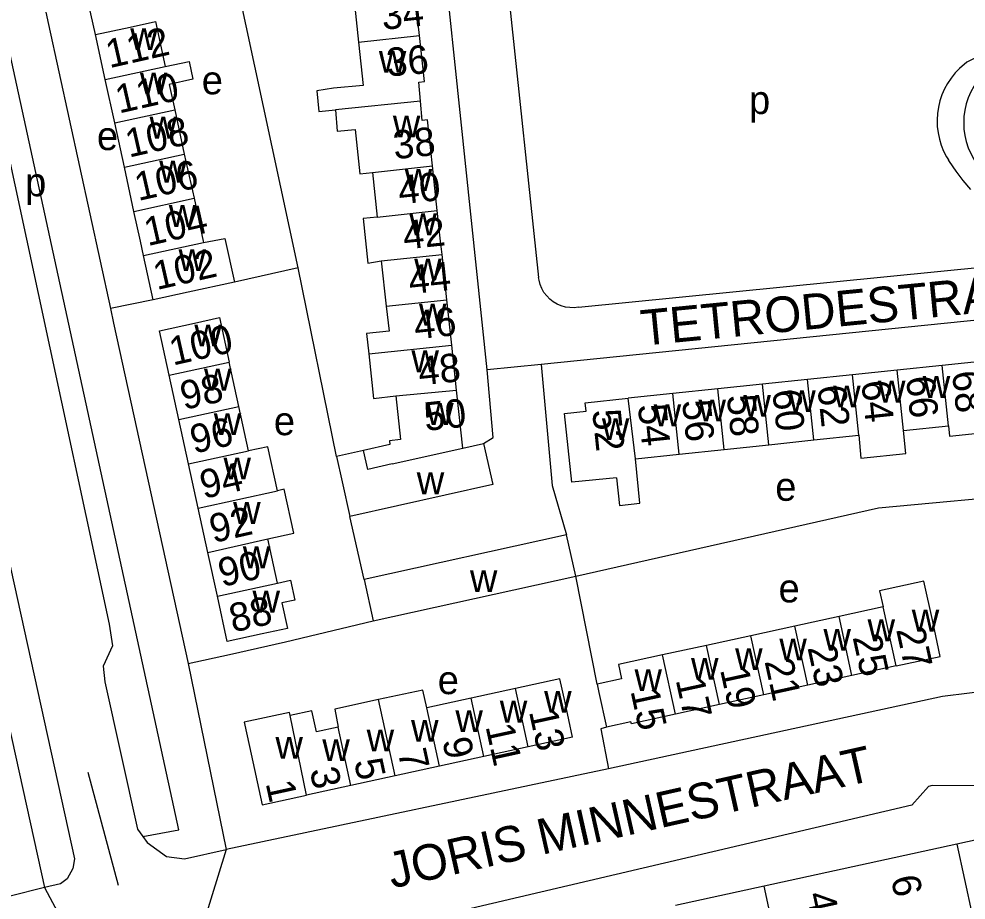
# Model space of a CAD drawing. Extents: x 159294 to 161936, y 384538 to 386517.
# Drawn here: x 160707.3 to 160840.4, y 385907.4 to 386031.2 of the extents above; entities that cross this region are included whole.
import ezdxf

# ---------------------------------------------------------------- set-up
doc = ezdxf.new("R2010")
doc.units = 0
for name, color, linetype in [('BLT_Basislijn', 7, 'Continuous'), ('BLT_Bebouwing', 7, 'Continuous'), ('BLT_Centroide', 7, 'Continuous'), ('BLT_Huisnummer', 7, 'Continuous'), ('BLT_Huisnummer_ tussenligend', 7, 'Continuous'), ('BLT_Huisnummer_reeks', 7, 'Continuous'), ('BLT_Onderverdeling_panden', 7, 'Continuous'), ('BLT_Straatnaam', 7, 'Continuous'), ('BLT_Vlakafsluiter', 7, 'Continuous')]:
    doc.layers.add(name, color=color, linetype=linetype)

msp = doc.modelspace()

# ---------------------------------------------------------------- linework, layer by layer
at = {"layer": 'BLT_Basislijn'}
for p, q in [((160775.29, 386042.75), (160780.36, 385994.88)), ((160718.09, 386029.02), (160717.12, 386033.4)), ((160746.59, 385996.22), (160737.63, 385994.24)), ((160751.96, 385969.73), (160746.59, 385996.22)), ((160785.98, 385990.69), (160850.47, 385997.12)), ((160726.21, 385991.76), (160720.2, 385990.52)), ((160780.73, 385982.66), (160773.13, 385981.91)), ((160755.85, 385952.43), (160753.85, 385961.28)), ((160700, 385958.71), (160710.91, 385909.14)), ((160788.57, 385937.7), (160785.58, 385952.89)), ((160731.13, 385940.64), (160736.48, 385914.45)), ((160789.89, 385931.66), (160789.11, 385931.43)), ((160789.11, 385931.43), (160790.19, 385925.81)), ((160790.19, 385925.81), (160736.48, 385914.45)), ((160717.03, 385925.33), (160721.29, 385909.44)), ((160710.91, 385909.14), (160706.13, 385907.93))]:
    msp.add_line(p, q, dxfattribs=at)
for points in [[(160773.13, 385981.91), (160763.33, 386075.31), (160762.11, 386075.61)], [(160724.75, 385916.3), (160729.82, 385917.26), (160700, 386054.05)], [(160700, 386039.15), (160720.02, 385946.17), (160720.5, 385943.08), (160719.17, 385940.25), (160719.41, 385938.04), (160724, 385917.35), (160724.75, 385916.3)], [(160746.59, 385996.22), (160738.06, 386035.99), (160737.84, 386037.75)], [(160711.11, 386032.17), (160711.48, 386030.46), (160720.2, 385990.52)], [(160851.41, 386028.7), (160847.92, 386027.88), (160845.04, 386025.75), (160842.92, 386026.31), (160840.52, 386025.15), (160839.52, 386024.28)], [(160839.52, 386024.28), (160838.89, 386023.63), (160838.33, 386022.92), (160837.82, 386022.17), (160837.39, 386021.38), (160837.03, 386020.55), (160836.74, 386019.7), (160836.54, 386018.82), (160836.4, 386017.92), (160836.35, 386017.02), (160836.38, 386016.12), (160836.49, 386015.22), (160836.68, 386014.34), (160836.94, 386013.48), (160837.28, 386012.64), (160837.7, 386011.84), (160837.94, 386011.44)], [(160842.01, 386022.49), (160841.52, 386021.74), (160841.09, 386020.96), (160840.74, 386020.14), (160840.46, 386019.29), (160840.26, 386018.41), (160840.14, 386017.53), (160840.1, 386016.64), (160840.14, 386015.74), (160840.26, 386014.86), (160840.45, 386013.98), (160840.73, 386013.13), (160841.08, 386012.31), (160841.5, 386011.52), (160841.99, 386010.77), (160842.54, 386010.07), (160843.15, 386009.42), (160843.83, 386008.83), (160844.55, 386008.3), (160845.31, 386007.84), (160846.12, 386007.45), (160846.6, 386007.26)], [(160841.11, 386007.25), (160840.04, 386008.51), (160839.04, 386009.83), (160838.1, 386011.19), (160837.94, 386011.44)], [(160785.98, 385990.69), (160785.36, 385990.62), (160784.74, 385990.64), (160784.12, 385990.73), (160783.52, 385990.9), (160782.96, 385991.15), (160782.42, 385991.47), (160781.93, 385991.85), (160781.5, 385992.3), (160781.12, 385992.79), (160780.81, 385993.33), (160780.58, 385993.91), (160780.42, 385994.51), (160780.36, 385994.88)], [(160720.2, 385990.52), (160720.65, 385988.45), (160731.13, 385940.64)], [(160859.23, 385988.45), (160858.82, 385990.52), (160856.7, 385990.38), (160780.73, 385982.66)], [(160700, 385981.81), (160715.13, 385913.15), (160714.89, 385911.82), (160714.13, 385910.35), (160713.17, 385909.64), (160710.91, 385909.14)], [(160772.63, 385971.54), (160773.97, 385972.4), (160773.13, 385981.91)], [(160780.73, 385982.66), (160782.28, 385965.66), (160784.3, 385958.7)], [(160785.58, 385952.89), (160828.14, 385962.5), (160850.38, 385964.54), (160853.69, 385964.6), (160860.01, 385962.42)], [(160731.13, 385940.64), (160736.91, 385941.89), (160744.81, 385943.68), (160757.12, 385946.62)], [(160887.99, 385925.36), (160883.44, 385926.7), (160883.29, 385928.09), (160883.51, 385928.54), (160861.9, 385934.99), (160852.41, 385936.78), (160844.7, 385936.94), (160837.12, 385935.98), (160790.19, 385925.81)], [(160878.09, 385873.27), (160882.75, 385872.03), (160884.03, 385872.93), (160885.3, 385874.52), (160884.95, 385877.35), (160895.88, 385895.1), (160896.53, 385895.86), (160901.29, 385903.4), (160899.44, 385905.93), (160897.31, 385907.67), (160894.48, 385908.01), (160892.15, 385906.21), (160890.48, 385906.26), (160855.53, 385917.61), (160853.29, 385921.28), (160852.6, 385921.78), (160843.49, 385923.4), (160835.67, 385923.48), (160835.16, 385923.35), (160832.82, 385920.7), (160749.73, 385901.19), (160744.7, 385901.94), (160733.87, 385898.4), (160732.63, 385897.5)], [(160724.75, 385916.3), (160725.35, 385915.47), (160728.08, 385913.47), (160730.62, 385913.14), (160736.48, 385914.45)]]:
    msp.add_lwpolyline(points, dxfattribs=at)
at = {"layer": 'BLT_Bebouwing'}
for p, q in [((160763.61, 386028.9), (160762.92, 386035.21)), ((160754.38, 386034.29), (160755.06, 386027.98)), ((160719.46, 386022.7), (160718.09, 386029.02)), ((160720.8, 386016.6), (160719.46, 386022.7)), ((160763.99, 386016.94), (160763.76, 386019.65)), ((160729.23, 386018.44), (160730.58, 386012.23)), ((160722.15, 386010.39), (160720.8, 386016.6)), ((160730.58, 386012.23), (160731.94, 386006.02)), ((160723.5, 386004.18), (160722.15, 386010.39)), ((160757.01, 386009.66), (160757.67, 386003.37)), ((160766.13, 386004.28), (160765.46, 386010.57)), ((160726.21, 385991.76), (160724.86, 385997.97)), ((160767.48, 385991.74), (160766.8, 385998.1)), ((160758.26, 385997.2), (160758.94, 385990.84)), ((160768.16, 385985.38), (160767.48, 385991.74)), ((160728.46, 385981.16), (160727.1, 385987.4)), ((160768.84, 385979.03), (160768.16, 385985.38)), ((160738.25, 385976.76), (160736.89, 385983)), ((160843.36, 385983.18), (160837.06, 385982.52)), ((160830.75, 385981.86), (160824.45, 385981.2)), ((160837.06, 385982.52), (160830.75, 385981.86)), ((160729.82, 385974.93), (160728.46, 385981.16)), ((160818.15, 385980.55), (160811.84, 385979.89)), ((160824.45, 385981.2), (160818.15, 385980.55)), ((160769.72, 385970.89), (160768.84, 385979.03)), ((160805.54, 385979.23), (160799.23, 385978.57)), ((160811.84, 385979.89), (160805.54, 385979.23)), ((160786.9, 385977.28), (160792.93, 385977.91)), ((160799.23, 385978.57), (160792.93, 385977.91)), ((160739.61, 385970.53), (160738.25, 385976.76)), ((160731.18, 385968.69), (160729.82, 385974.93)), ((160831.64, 385973.36), (160837.95, 385974.02)), ((160819.04, 385972.04), (160825.34, 385972.7)), ((160769.72, 385970.89), (160772.63, 385971.54)), ((160806.43, 385970.72), (160812.73, 385971.38)), ((160812.73, 385971.38), (160819.04, 385972.04)), ((160793.96, 385969.41), (160800.12, 385970.06)), ((160800.12, 385970.06), (160806.43, 385970.72)), ((160732.54, 385962.45), (160731.18, 385968.69)), ((160791.33, 385966.74), (160785.03, 385966.09)), ((160733.9, 385956.21), (160732.54, 385962.45)), ((160743.67, 385951.93), (160742.32, 385958.12)), ((160784.3, 385958.7), (160755.85, 385952.43)), ((160785.58, 385952.89), (160784.3, 385958.7)), ((160735.24, 385950.09), (160733.9, 385956.21)), ((160755.85, 385952.43), (160757.12, 385946.62)), ((160757.12, 385946.62), (160785.58, 385952.89)), ((160828.78, 385948.6), (160822.58, 385947.24)), ((160822.58, 385947.24), (160816.38, 385945.89)), ((160816.38, 385945.89), (160810.18, 385944.53)), ((160810.18, 385944.53), (160803.98, 385943.17)), ((160803.98, 385943.17), (160797.77, 385941.82)), ((160830.61, 385940.27), (160824.4, 385938.91)), ((160824.4, 385938.91), (160818.2, 385937.55)), ((160818.2, 385937.55), (160812, 385936.2)), ((160777.12, 385937.11), (160770.89, 385935.76)), ((160812, 385936.2), (160805.8, 385934.84)), ((160770.89, 385935.76), (160764.66, 385934.4)), ((160805.8, 385934.84), (160799.6, 385933.48)), ((160785.14, 385930.25), (160778.92, 385928.89)), ((160778.92, 385928.89), (160772.69, 385927.53)), ((160772.69, 385927.53), (160766.45, 385926.17)), ((160766.45, 385926.17), (160760.22, 385924.81)), ((160760.22, 385924.81), (160753.99, 385923.46)), ((160753.99, 385923.46), (160747.76, 385922.1)), ((160839.15, 385915.21), (160812.05, 385909.31)), ((160812.05, 385909.31), (160799.6, 385906.6))]:
    msp.add_line(p, q, dxfattribs=at)
for points in [[(160718.09, 386029.02), (160722.97, 386030.09), (160726.52, 386030.86), (160727.9, 386024.54)], [(160763.76, 386019.65), (160763.53, 386022.32), (160764.31, 386022.41), (160763.61, 386028.9)], [(160755.06, 386027.98), (160755.72, 386021.87), (160751.52, 386021.48), (160749.21, 386021.12), (160749.5, 386018.21), (160751.8, 386018.44)], [(160727.9, 386024.54), (160731.24, 386025.26), (160731.79, 386022.75), (160728.45, 386022.02), (160729.23, 386018.44)], [(160751.8, 386018.44), (160752.08, 386015.47), (160754.59, 386015.7)], [(160765.46, 386010.57), (160764.77, 386017.02), (160763.99, 386016.94)], [(160754.59, 386015.7), (160755.25, 386009.47), (160757.01, 386009.66)], [(160731.94, 386006.02), (160733.25, 386000), (160733.29, 385999.81)], [(160724.86, 385997.97), (160724.42, 386000), (160723.5, 386004.18)], [(160766.8, 385998.1), (160766.59, 386000), (160766.13, 386004.28)], [(160757.67, 386003.37), (160755.7, 386003.16), (160756.36, 385996.88), (160758.26, 385997.2)], [(160733.29, 385999.81), (160736.29, 386000.37), (160737.63, 385994.24)], [(160737.63, 385994.24), (160731.1, 385992.82), (160726.21, 385991.76)], [(160758.94, 385990.84), (160759.35, 385987.33), (160756.19, 385986.99), (160756.49, 385984.17)], [(160727.1, 385987.4), (160731.99, 385988.47), (160735.53, 385989.24), (160736.89, 385983)], [(160756.49, 385984.17), (160757.16, 385977.89), (160760.31, 385978.23)], [(160760.31, 385978.23), (160760.95, 385972.09), (160759.42, 385971.93), (160759.48, 385971.41), (160755.75, 385970.58)], [(160785.03, 385966.09), (160784.02, 385975.76), (160787.03, 385976.08), (160786.9, 385977.28)], [(160837.95, 385974.02), (160838.1, 385972.56), (160844.4, 385973.22), (160844.25, 385974.68)], [(160825.34, 385972.7), (160825.64, 385969.46), (160831.98, 385970.12), (160831.64, 385973.36)], [(160743.66, 385964.89), (160742.31, 385971.09), (160739.61, 385970.53)], [(160772.63, 385971.54), (160773.92, 385965.76), (160753.85, 385961.28)], [(160755.75, 385970.58), (160751.96, 385969.73)], [(160751.96, 385969.73), (160752.76, 385966.16), (160753.85, 385961.28)], [(160791.33, 385966.74), (160791.74, 385962.84), (160794.61, 385963.14), (160793.96, 385969.41)], [(160742.32, 385958.12), (160745.98, 385958.92), (160744.63, 385965.11), (160743.66, 385964.89)], [(160743.67, 385951.93), (160745.48, 385952.32), (160746.09, 385949.53), (160744.28, 385949.14), (160745.06, 385945.56), (160741.51, 385944.79), (160736.62, 385943.73), (160735.24, 385950.09)], [(160830.61, 385940.27), (160836.81, 385941.62), (160835.74, 385946.51), (160834.49, 385952.21), (160828.28, 385950.85), (160828.78, 385948.6)], [(160797.77, 385941.82), (160791.57, 385940.46), (160792.01, 385938.46), (160788.57, 385937.7)], [(160785.14, 385930.25), (160784.08, 385935.13), (160783.35, 385938.47), (160777.12, 385937.11)], [(160788.57, 385937.7), (160788.82, 385936.55), (160789.89, 385931.66)], [(160764.66, 385934.4), (160764.09, 385936.89), (160757.88, 385935.54)], [(160757.88, 385935.54), (160751.72, 385934.2), (160752.2, 385931.68)], [(160745.44, 385933.31), (160745.34, 385933.75), (160738.99, 385932.38), (160739.73, 385928.96)], [(160752.2, 385931.68), (160749.16, 385931.02), (160748.51, 385933.98), (160745.44, 385933.31)], [(160799.6, 385933.48), (160793.4, 385932.12), (160793.33, 385932.42), (160789.89, 385931.66)], [(160739.73, 385928.96), (160741.52, 385920.74), (160747.76, 385922.1)], [(160854.91, 385912.23), (160843.2, 385916.09), (160839.15, 385915.21)]]:
    msp.add_lwpolyline(points, dxfattribs=at)
at = {"layer": 'BLT_Onderverdeling_panden'}
for p, q in [((160755.06, 386027.98), (160763.61, 386028.9)), ((160719.46, 386022.7), (160727.9, 386024.54)), ((160763.76, 386019.65), (160751.8, 386018.44)), ((160720.8, 386016.6), (160729.23, 386018.44)), ((160722.15, 386010.39), (160730.58, 386012.23)), ((160757.01, 386009.66), (160765.46, 386010.57)), ((160723.5, 386004.18), (160731.94, 386006.02)), ((160757.67, 386003.37), (160766.13, 386004.28)), ((160724.86, 385997.97), (160733.29, 385999.81)), ((160758.26, 385997.2), (160766.8, 385998.1)), ((160758.94, 385990.84), (160767.48, 385991.74)), ((160756.49, 385984.17), (160768.16, 385985.38)), ((160728.46, 385981.16), (160736.89, 385983)), ((160831.64, 385973.36), (160830.75, 385981.86)), ((160837.95, 385974.02), (160837.06, 385982.52)), ((160819.04, 385972.04), (160818.15, 385980.55)), ((160825.34, 385972.7), (160824.45, 385981.2)), ((160760.31, 385978.23), (160768.84, 385979.03)), ((160806.43, 385970.72), (160805.54, 385979.23)), ((160812.73, 385971.38), (160811.84, 385979.89)), ((160793.96, 385969.41), (160792.93, 385977.91)), ((160800.12, 385970.06), (160799.23, 385978.57)), ((160729.82, 385974.93), (160738.25, 385976.76)), ((160759.77, 385968.67), (160769.72, 385970.89)), ((160731.18, 385968.69), (160739.61, 385970.53)), ((160732.54, 385962.45), (160743.66, 385964.89)), ((160733.9, 385956.21), (160742.32, 385958.12)), ((160735.24, 385950.09), (160743.67, 385951.93)), ((160830.61, 385940.27), (160828.78, 385948.6)), ((160824.4, 385938.91), (160822.58, 385947.24)), ((160818.2, 385937.55), (160816.38, 385945.89)), ((160812, 385936.2), (160810.18, 385944.53)), ((160805.8, 385934.84), (160803.98, 385943.17)), ((160799.6, 385933.48), (160797.77, 385941.82)), ((160778.92, 385928.89), (160777.12, 385937.11)), ((160760.22, 385924.81), (160757.88, 385935.54)), ((160772.69, 385927.53), (160770.89, 385935.76)), ((160766.45, 385926.17), (160764.66, 385934.4)), ((160747.76, 385922.1), (160745.44, 385933.31)), ((160753.99, 385923.46), (160752.2, 385931.68)), ((160813.9, 385900.78), (160812.05, 385909.31))]:
    msp.add_line(p, q, dxfattribs=at)
for points in [[(160759.77, 385968.67), (160756.35, 385967.91), (160755.75, 385970.58)], [(160839.15, 385915.21), (160841.29, 385905.3)]]:
    msp.add_lwpolyline(points, dxfattribs=at)
at = {"layer": 'BLT_Vlakafsluiter'}
for p, q in [((160736.48, 385914.45), (160733.17, 385903.85)), ((160710.91, 385909.14), (160715.96, 385899.78))]:
    msp.add_line(p, q, dxfattribs=at)

# ---------------------------------------------------------------- texts
at = {"layer": 'BLT_Centroide'}
for s, p in [('w', (160722.98, 386026.84)), ('w', (160757.91, 386023.67)), ('w', (160724.34, 386020.62)), ('e', (160733.03, 386020.63)), ('p', (160809.93, 386017.86)), ('w', (160725.69, 386014.41)), ('w', (160759.88, 386014.56)), ('e', (160718.3, 386012.79)), ('w', (160727.05, 386008.22)), ('p', (160708.2, 386006.3)), ('w', (160761.55, 386007.06)), ('w', (160728.4, 386002)), ('w', (160762.19, 386000.81)), ('w', (160729.76, 385995.78)), ('w', (160762.88, 385994.47)), ('w', (160763.55, 385988.12)), ('w', (160731.99, 385985.19)), ('w', (160762.49, 385981.56)), ('w', (160733.35, 385978.97)), ('w', (160828.05, 385977.3)), ('w', (160834.34, 385977.95)), ('w', (160815.44, 385975.95)), ('w', (160821.75, 385976.61)), ('w', (160802.83, 385974.64)), ('w', (160809.14, 385975.3)), ('w', (160764.56, 385974.16)), ('w', (160796.53, 385973.98)), ('w', (160734.72, 385972.72)), ('e', (160743.16, 385972.71)), ('w', (160789.25, 385972.03)), ('w', (160736.08, 385966.5)), ('w', (160763.24, 385964.41)), ('e', (160813.62, 385963.49)), ('w', (160737.44, 385960.25)), ('w', (160738.8, 385954)), ('w', (160770.71, 385950.66)), ('e', (160814.08, 385949.21)), ('w', (160740.16, 385947.78)), ('w', (160832.8, 385945.11)), ('w', (160826.59, 385943.75)), ('w', (160820.39, 385942.41)), ('w', (160814.19, 385941.05)), ('w', (160807.98, 385939.69)), ('w', (160801.78, 385938.33)), ('e', (160766.19, 385936.31)), ('w', (160793.84, 385936.75)), ('w', (160781.14, 385933.69)), ('w', (160774.91, 385932.31)), ('w', (160768.67, 385930.97)), ('w', (160762.44, 385929.61)), ('w', (160756.2, 385928.25)), ('w', (160743.38, 385927.23)), ('w', (160749.97, 385926.89))]:
    msp.add_text(s, height=4, dxfattribs=at).set_placement(p)
at = {"layer": 'BLT_Huisnummer'}
for s, rotation, p in [('112', 12.7604, (160720.05, 386024.29)), ('36', 4.897, (160759.13, 386023.12)), ('38', 6.0153, (160760.11, 386011.49)), ('106', 12.7604, (160724.1, 386005.62)), ('42', 6.0139, (160761.5, 385998.8)), ('102', 12.7604, (160726.71, 385993.11)), ('46', 6.0125, (160763.05, 385986.17)), ('100', 12.7604, (160728.97, 385982.49)), ('68', 275.9596, (160838.46, 385981.61)), ('64', 275.9596, (160825.71, 385980.27)), ('60', 275.9596, (160813.2, 385979.01)), ('50', 6.12, (160764.45, 385973.3)), ('56', 275.9596, (160800.52, 385977.54)), ('52', 275.9596, (160787.89, 385976.2)), ('96', 12.7604, (160731.91, 385970.1)), ('92', 12.7604, (160734.63, 385957.54)), ('88', 12.7604, (160737.4, 385944.96)), ('27', 282.3436, (160830.59, 385945.39)), ('23', 282.3436, (160818.13, 385942.86)), ('19', 282.3436, (160805.85, 385939.76)), ('15', 282.3436, (160793.26, 385936.77)), ('13', 282.2977, (160778.99, 385933.87)), ('9', 282.2977, (160766.81, 385929.82)), ('5', 282.2977, (160754.41, 385926.87)), ('1', 282.2977, (160741.99, 385923.79))]:
    msp.add_text(s, height=4, rotation=rotation, dxfattribs=at).set_placement(p)
at = {"layer": 'BLT_Huisnummer_ tussenligend'}
for s, rotation, p in [('34', 6.1619, (160758.48, 386029.67)), ('110', 12.7604, (160721.4, 386017.92)), ('108', 12.7604, (160722.8, 386011.72)), ('40', 6.0153, (160760.83, 386005.15)), ('104', 12.7604, (160725.43, 385999.28)), ('44', 6.0139, (160762.28, 385992.53)), ('48', 6.0125, (160763.65, 385979.7)), ('98', 12.7604, (160730.52, 385976.24)), ('66', 275.9596, (160831.99, 385980.87)), ('62', 275.9596, (160819.54, 385979.6)), ('58', 275.9596, (160806.8, 385978.26)), ('54', 275.9596, (160794.3, 385976.94)), ('94', 12.7604, (160733.28, 385963.74)), ('90', 12.7604, (160735.86, 385951.36)), ('25', 282.3436, (160824.47, 385944.33)), ('21', 282.3436, (160812.1, 385940.93)), ('17', 282.3436, (160799.61, 385938.32)), ('11', 282.2977, (160772.89, 385931.78)), ('7', 282.2977, (160760.55, 385928.22)), ('3', 282.2977, (160748.18, 385925.63))]:
    msp.add_text(s, height=4, rotation=rotation, dxfattribs=at).set_placement(p)
at = {"layer": 'BLT_Huisnummer_reeks'}
for s, rotation, p in [('6', 282.2782, (160829.84, 385910.45)), ('4', 282.292, (160817.97, 385908.15))]:
    msp.add_text(s, height=4, rotation=rotation, dxfattribs=at).set_placement(p)
at = {"layer": 'BLT_Straatnaam'}
for s, height, rotation, p in [('TETRODESTRAAT', 5, 5.5777, (160794.96, 385985.28)), ('JORIS MINNESTRAAT', 4.9999, 12.6789, (160759.77, 385908.98))]:
    msp.add_text(s, height=height, rotation=rotation, dxfattribs=at).set_placement(p)

doc.saveas('drawing.dxf')
